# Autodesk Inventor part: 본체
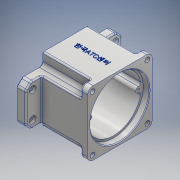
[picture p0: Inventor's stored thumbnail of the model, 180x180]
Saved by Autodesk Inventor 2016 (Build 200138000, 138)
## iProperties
Created: 2017-01
Part Number: 본체
Material: 알루미늄 6061
Document SubType Name: Modeling
Designer: Owner
Density: 2.7 g/cm^3
Appearance: 알루미늄 - 평지
Mass: 877.754 g
Surface Area: 763.669 cm^2
Volume: 325.094 cm^3
Author: Owner
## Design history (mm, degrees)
sketch "스케치4"
  geometry: L1 (70, -30)-(70, 30); L2 (-70, -30)-(-70, 30); L3 (-33, -47)-(33, -47); L4 (33, 47)-(-33, 47); L5 (70, 30)-(33, 30); L6 (-33, -30)-(-70, -30); L7 (-33, 47)-(-33, 30); L8 (-33, -30)-(-33, -47); L9 (-70, 30)-(-33, 30); L10 (33, -30)-(70, -30); L11 (33, -47)-(33, -30); L12 (33, 30)-(33, 47); 5 further points
  constraints: 24 end point, 10 equal length, 4 midpoint, 4 perpendicular, 3 horizontal, 2 collinear, 2 horizontal alignment, 2 vertical alignment
  dimensions: "d6" = 66 distance of L4.start L4.end; "d7" = 60 distance of L1.start L1.end; "d8" = 60 distance of L2.start L2.end; "d9" = 66 distance of L3.start L3.end; "d10" = 94 distance between parallel lines of L3 L4; "d11" = 140 distance between parallel lines of L1 L2
extrude "돌출2" new body sketch "스케치4" distance "d12" = 13; taper "d13" = 0 deg
sketch "스케치6"
  geometry: L1 (-33, 47)-(33, 47); L2 (33, 47)-(33, -47); L3 (33, -47)-(-33, -47); L4 (-33, -47)-(-33, 47); L5 (-33, 47)-(33, -47); L6 (33, 47)-(-33, -47); 1 further point
  constraints: 12 end point, 2 midpoint, 2 parallel, 1 horizontal, 1 perpendicular
extrude "돌출3" join sketch "스케치6" distance "d16" = 80; taper "d17" = 0 deg
sketch "스케치7"
  geometry: C1 r 27.5 at (11, 0); 2 further points
  constraints: 1 centre point, 1 coincident, 1 horizontal alignment
  dimensions: "d18" = 11 distance of point (11, 0) point (0, 0); "d19" = 55 diameter of C1
extrude "돌출4" join sketch "스케치7" distance "d20" = 7; taper "d21" = 0 deg
hole "구멍1" diameter "d24" = 32; stored, may be unused: countersink angle "d28" = 90 deg, drill point angle "d30" = 0 deg; dims "d25" = 6, "d26" = 4, "d27" = 2, "d29" = 8, "d31" = 10, "d32" = 10
hole "구멍2" diameter "d35" = 25; stored, may be unused: countersink angle "d39" = 90 deg, drill point angle "d41" = 0 deg; dims "d36" = 6, "d37" = 4, "d38" = 2, "d40" = 5, "d42" = 10, "d43" = 10
sketch "스케치8"
  geometry: L1 (-47, -47)-(47, -47); L2 (47, -47)-(47, 47); L3 (47, 47)-(-47, 47); L4 (-47, 47)-(-47, -47); L5 (-47, -47)-(47, 47); L6 (47, -47)-(-47, 47); 1 further point
  constraints: 12 end point, 2 midpoint, 2 parallel, 1 horizontal, 1 perpendicular
  dimensions: "d44" = 94 distance of L3.end L1.start; "d45" = 94 distance of L2.end L3.end
extrude "돌출5" join sketch "스케치8" distance "d46" = 10; taper "d47" = 0 deg
sketch "스케치9"
  geometry: L1 (30, 33)-(30, 70) reference; L2 (-30, -47)-(30, -47); L3 (30, -47)-(30, 47); L4 (30, 47)-(-30, 47); L5 (-30, 47)-(-30, -47); L6 (-30, -47)-(30, 47); L7 (30, -47)-(-30, 47); 1 further point
  constraints: 12 end point, 2 midpoint, 2 parallel, 1 horizontal, 1 perpendicular, 1 point on line
  dimensions: "d48" = 94 distance of L4.end L2.start
extrude "돌출6" join sketch "스케치9" stored distance "d49" = 10; taper "d50" = 0 deg
sketch "스케치10"
  geometry: 2 further points
  constraints: 1 coincident
hole "구멍3" sketch "스케치10" at (0, 0) diameter "d51" = 80; stored, may be unused: countersink angle "d55" = 90 deg, drill point angle "d57" = 0 deg; dims "d52" = 6, "d53" = 4, "d54" = 2, "d56" = 71
sketch "스케치11"
  geometry: A1 r 21 centre (-11, 0) between (7.984, 8.978) and (7.984, -8.978); A2 r 15 centre (20, 0) between (7.984, -8.978) and (7.984, 8.978); 3 further points
  constraints: 4 point on circle, 2 centre point, 2 coincident, 1 horizontal alignment
  dimensions: "d58" = 42 diameter of A1; "d71" = 20 distance of point (20, 0) point (0, 0); "d72" = 30 diameter of A2
extrude "돌출7" join sketch "스케치11" distance "d59" = 7; taper "d60" = 0 deg
hole "구멍4" diameter "d63" = 35; stored, may be unused: countersink angle "d67" = 90 deg, drill point angle "d69" = 0 deg; dims "d61" = 10, "d62" = 10, "d64" = 6, "d65" = 4, "d66" = 2, "d68" = 10
fillet "모깎기1" dims "d70" = 0.3
hole "구멍5" diameter "d75" = 22; stored, may be unused: countersink angle "d79" = 90 deg, drill point angle "d81" = 0 deg; dims "d73" = 10, "d74" = 10, "d76" = 6, "d77" = 4, "d78" = 2, "d80" = 7
hole "구멍6" diameter "d84" = 19; stored, may be unused: countersink angle "d88" = 90 deg, drill point angle "d90" = 0 deg; dims "d82" = 10, "d83" = 10, "d85" = 6, "d86" = 4, "d87" = 2, "d89" = 1
fillet "모깎기2" dims "d91" = 0.3
fillet "모깎기3" dims "d92" = 2
hole "구멍7" diameter "d95" = 86; stored, may be unused: countersink angle "d99" = 90 deg, drill point angle "d101" = 0 deg; dims "d93" = 10, "d94" = 10, "d96" = 6, "d97" = 4, "d98" = 2, "d100" = 9
fillet "모깎기4" dims "d102" = 0.3
chamfer "모따기1" distance "d103" = 1; stored, may be unused: second distance "d104" = 2, angle "d105" = 45 deg
sketch "스케치12"
  geometry: C1 r 43 at (0, 0); A1 r 36 centre (0, 0) between (0, 36) and (0, -36); A2 r 4 centre (0, 36) between (-3.997, 35.852) and (3.997, 35.852); A3 r 4 centre (0, -36) between (3.997, -35.852) and (-3.997, -35.852); A4 r 3.5 centre (-7.495, 35.722) between (-3.995, 35.778) and (-8.214, 39.148); A5 r 3.5 centre (7.495, 35.722) between (8.214, 39.148) and (3.995, 35.778); A6 r 3.5 centre (7.495, -35.722) between (3.995, -35.778) and (8.214, -39.148); A7 r 40 centre (0, 0) between (-8.214, 39.148) and (-8.214, -39.148); A8 r 40 centre (0, 0) between (8.214, -39.148) and (8.214, 39.148); A9 r 3.5 centre (-7.495, -35.722) between (-8.214, -39.148) and (-3.995, -35.778); 1 further point
  constraints: 26 point on circle, 10 centre point, 5 tangent, 4 vertical alignment, 3 coincident, 1 horizontal alignment
  dimensions: "d106" = 72 diameter of A1; "d107" = 8 diameter of A2; "d108" = 8 diameter of A3; "d111" = 3.5 radius of A4; "d112" = 3.5 radius of A5; "d113" = 3.5 radius of A6; "d114" = 7 diameter of A9; "d115" = 40 radius of A7; "d116" = 40 radius of A8; "d117" = 86 diameter of C1
extrude "돌출8" join sketch "스케치12" distance "d118" = 62; taper "d119" = 0 deg
sketch "스케치13"
  geometry: 2 further points
  dimensions: "d120" = 60 vertical distance of point (0, 0) point (-19, -60); "d121" = 19 horizontal distance of point (0, 0) point (-19, -60)
hole "구멍8" sketch "스케치13" at (-19, -60) diameter "d122" = 4; stored, may be unused: countersink angle "d126" = 90 deg, drill point angle "d128" = 0 deg; dims "d123" = 6, "d124" = 4, "d125" = 2, "d127" = 9
hole "구멍9" diameter "d131" = 10; stored, may be unused: countersink angle "d135" = 90 deg, drill point angle "d137" = 0 deg; dims "d132" = 6, "d133" = 4, "d134" = 2, "d136" = 4, "d138" = 10, "d139" = 10
fillet "모깎기5" dims "d140" = 8
chamfer "모따기2" distance "d141" = 8; stored, may be unused: second distance "d142" = 2, angle "d143" = 45 deg
fillet "모깎기6" dims "d144" = 5
chamfer "모따기3" distance "d145" = 1; stored, may be unused: second distance "d146" = 2, angle "d147" = 45 deg
fillet "모깎기7" dims "d148" = 5
hole "구멍10" diameter "d151" = 3.242; stored, may be unused: countersink angle "d155" = 90 deg, drill point angle "d157" = 118 deg; dims "d152" = 7, "d153" = 4, "d154" = 2, "d156" = 10.8, "d187" = 10, "d188" = 10
sketch "스케치14"
  geometry: 2 further points
  dimensions: "d160" = 40 horizontal distance of point (0, 0) point (-40, 40); "d161" = 40 horizontal distance of point (0, 0) point (-40, 40)
hole "구멍11" sketch "스케치14" at (-40, 40) diameter "d162" = 7; stored, may be unused: countersink angle "d166" = 90 deg, drill point angle "d168" = 0 deg; dims "d163" = 8, "d164" = 4, "d165" = 2, "d167" = 9
fillet "모깎기8" dims "d172" = 2
fillet "모깎기9" dims "d173" = 3
fillet "모깎기10" dims "d174" = 2
fillet "모깎기11" dims "d175" = 2
fillet "모깎기12" dims "d176" = 2
fillet "모깎기13" dims "d177" = 2
fillet "모깎기14" dims "d178" = 2
fillet "모깎기15" dims "d179" = 2
sketch "스케치15"
  geometry: L1 (-80, 70)-(-80, 8) reference; L2 (0, 78)-(0, 0) reference; 3 further points
  constraints: 1 horizontal alignment, 1 midpoint, 1 other
  dimensions: "d180" = 40 distance from line of L2 point (-40, 39)
feature "엠보싱1" sketch "스케치15" dims "d181" = 0.5, "d182" = 0
sketch "스케치16"
  geometry: L1 (35, 33)-(45, 33) reference; L2 (30, 59.929)-(30, 38) reference; L3 (23.464, 68.536)-(28.536, 63.464) reference; L4 (-19.929, 70)-(19.929, 70) reference; L5 (-28.536, 63.464)-(-23.464, 68.536) reference; L6 (-30, 38)-(-30, 59.929) reference; L7 (-45, 33)-(-35, 33) reference; L8 (-47, -31)-(-47, 31) reference; L9 (-35, -33)-(-45, -33) reference; L10 (-30, -59.929)-(-30, -38) reference; L11 (-23.464, -68.536)-(-28.536, -63.464) reference; L12 (19.929, -70)-(-19.929, -70) reference; L13 (28.536, -63.464)-(23.464, -68.536) reference; L14 (30, -38)-(30, -59.929) reference; L15 (45, -33)-(35, -33) reference; L16 (47, 31)-(47, -31) reference; L17 (45, -32)-(35, -32); L18 (29, -38)-(29, -59.929); L19 (27.828, -62.757)-(22.757, -67.828); L20 (19.929, -69)-(-19.929, -69); L21 (-22.757, -67.828)-(-27.828, -62.757); L22 (-29, -59.929)-(-29, -38); L23 (-35, -32)-(-45, -32); L24 (-46, -31)-(-46, 31); L25 (-45, 32)-(-35, 32); L26 (-29, 38)-(-29, 59.929); L27 (-27.828, 62.757)-(-22.757, 67.828); L28 (-19.929, 69)-(19.929, 69); L29 (22.757, 67.828)-(27.828, 62.757); L30 (29, 59.929)-(29, 38); L31 (35, 32)-(45, 32); L32 (46, 31)-(46, -31); L33 (45, -33)-(35, -33); L34 (30, -38)-(30, -59.929); L35 (28.536, -63.464)-(23.464, -68.536); L36 (19.929, -70)-(-19.929, -70); L37 (-23.464, -68.536)-(-28.536, -63.464); L38 (-30, -59.929)-(-30, -38); L39 (-35, -33)-(-45, -33); L40 (-47, -31)-(-47, 31); L41 (-45, 33)-(-35, 33); L42 (-30, 38)-(-30, 59.929); L43 (-28.536, 63.464)-(-23.464, 68.536); L44 (-19.929, 70)-(19.929, 70); L45 (23.464, 68.536)-(28.536, 63.464); L46 (30, 59.929)-(30, 38); L47 (35, 33)-(45, 33); L48 (47, 31)-(47, -31); C1 r 2 at (-19, 60) reference; C2 r 2 at (-19, -60) reference; C3 r 2 at (19, 60) reference; C4 r 2 at (19, -60) reference; C5 r 27.8 at (11, 0) reference; A1 r 2 centre (45, 31) between (47, 31) and (45, 33) reference; A2 r 5 centre (35, 38) between (30, 38) and (35, 33) reference; A3 r 5 centre (25, 59.929) between (30, 59.929) and (28.536, 63.464) reference; A4 r 5 centre (19.929, 65) between (23.464, 68.536) and (19.929, 70) reference; A5 r 5 centre (-19.929, 65) between (-19.929, 70) and (-23.464, 68.536) reference; A6 r 5 centre (-25, 59.929) between (-28.536, 63.464) and (-30, 59.929) reference; A7 r 5 centre (-35, 38) between (-35, 33) and (-30, 38) reference; A8 r 2 centre (-45, 31) between (-45, 33) and (-47, 31) reference; A9 r 2 centre (-45, -31) between (-47, -31) and (-45, -33) reference; A10 r 5 centre (-35, -38) between (-30, -38) and (-35, -33) reference; A11 r 5 centre (-25, -59.929) between (-30, -59.929) and (-28.536, -63.464) reference; A12 r 5 centre (-19.929, -65) between (-23.464, -68.536) and (-19.929, -70) reference; A13 r 5 centre (19.929, -65) between (19.929, -70) and (23.464, -68.536) reference; A14 r 5 centre (25, -59.929) between (28.536, -63.464) and (30, -59.929) reference; A15 r 5 centre (35, -38) between (35, -33) and (30, -38) reference; A16 r 2 centre (45, -31) between (45, -33) and (47, -31) reference; A17 r 1 centre (45, -31) between (45, -32) and (46, -31); A18 r 6 centre (35, -38) between (35, -32) and (29, -38); A19 r 4 centre (25, -59.929) between (27.828, -62.757) and (29, -59.929); A20 r 4 centre (19.929, -65) between (19.929, -69) and (22.757, -67.828); A21 r 4 centre (-19.929, -65) between (-22.757, -67.828) and (-19.929, -69); A22 r 4 centre (-25, -59.929) between (-29, -59.929) and (-27.828, -62.757); A23 r 6 centre (-35, -38) between (-29, -38) and (-35, -32); A24 r 1 centre (-45, -31) between (-46, -31) and (-45, -32); A25 r 1 centre (-45, 31) between (-45, 32) and (-46, 31); A26 r 6 centre (-35, 38) between (-35, 32) and (-29, 38); A27 r 4 centre (-25, 59.929) between (-27.828, 62.757) and (-29, 59.929); A28 r 4 centre (-19.929, 65) between (-19.929, 69) and (-22.757, 67.828); A29 r 4 centre (19.929, 65) between (22.757, 67.828) and (19.929, 69); A30 r 4 centre (25, 59.929) between (29, 59.929) and (27.828, 62.757); A31 r 6 centre (35, 38) between (29, 38) and (35, 32); A32 r 1 centre (45, 31) between (46, 31) and (45, 32); A33 r 2 centre (45, -31) between (45, -33) and (47, -31); A34 r 5 centre (35, -38) between (35, -33) and (30, -38); A35 r 5 centre (25, -59.929) between (28.536, -63.464) and (30, -59.929); A36 r 5 centre (19.929, -65) between (19.929, -70) and (23.464, -68.536); A37 r 5 centre (-19.929, -65) between (-23.464, -68.536) and (-19.929, -70); A38 r 5 centre (-25, -59.929) between (-30, -59.929) and (-28.536, -63.464); A39 r 5 centre (-35, -38) between (-30, -38) and (-35, -33); A40 r 2 centre (-45, -31) between (-47, -31) and (-45, -33); A41 r 2 centre (-45, 31) between (-45, 33) and (-47, 31); A42 r 5 centre (-35, 38) between (-35, 33) and (-30, 38); A43 r 5 centre (-25, 59.929) between (-28.536, 63.464) and (-30, 59.929); A44 r 5 centre (-19.929, 65) between (-19.929, 70) and (-23.464, 68.536); A45 r 5 centre (19.929, 65) between (23.464, 68.536) and (19.929, 70); A46 r 5 centre (25, 59.929) between (30, 59.929) and (28.536, 63.464); A47 r 5 centre (35, 38) between (30, 38) and (35, 33); A48 r 2 centre (45, 31) between (47, 31) and (45, 33); 1 further point
  constraints: 64 end point, 64 point on circle, 32 centre point, 62 other
  dimensions: "d183" = 1 distance between parallel lines of L16 L32; "d184" = 1 distance between parallel lines of L32 L48
extrude "돌출9" cut sketch "스케치16" distance "d185" = 1; taper "d186" = 0 deg
node "솔리드2"
mirror "대칭1"
mirror "대칭2"
mirror "대칭3"
pattern_circular "원형 패턴1" dims angle "d170" = 360 deg
node "투영된 루프1"
